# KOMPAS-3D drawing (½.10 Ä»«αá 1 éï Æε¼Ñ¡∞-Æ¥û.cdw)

Views: Вид 1, Вид 2
Referenced files in J:\РП от РУ Великорецкая\5. Проект\ПОС\Линия\Чертежи\Рис\: кран 16 т.JPG
Referenced files: Подвеска ВЧ-заградителя.cdw
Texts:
  Текст на чертеже
  Размерные надписи
  Шероховатость
  Линия-выноска #1
  Линия-выноска #2
  Линия-выноска #3
  Отклонения формы и база
  Заголовок таблицы
  Ячейка таблицы
  Стрелка вида
  Обозначение изменения
  Фигурная скобка
  Номер узла
  Марка координационной оси
  VRCB
  Выносная надпись
  Обозначение узла
  Марка/позиционное обозначение с линией-выноской
  Марка/позиционное обозначение на линии
  Марка/позиционное обозначение без линии-выноски
  ООббыыччнныыйй
  Definition Term
  Definition List
  Address
  Blockquote
  Preformatted
  Courier New
  z-Bottom of Form
  z-Top of Form
  Лит-Масса-Масштаб
  Материал-Предприятие
  Title Specification
  Body Specification ( left align )
  Body Specificaton ( centered )
  Без имени
  SPEC
  Normal
  Txt
  Body Text
  heading 1
  Знак Знак Знак Знак Знак Знак
  Verdana
  Simplex
  TXT
  txt
  MS Sans Serif
  Additional DXF text style 0
  Обычный
  Термин
  Список определений
  Адрес
  Цитаты
  Форматированный
  Z-конец формы
  Z-начало формы
  ТекстШаг1
  Title
  Денис
  header
  heading 2
  AGOpus
  footer
  NormalParagraphStyle
  Body Text 3
  ссылки
  Подпись в квадратике
  табл
  цепи
  Маркировка
  клеммы, контакты
  тексты табл
  Тексты. 3,2
  ЗОНА_привяз
  текст переноса
  ТТееррммиинн
  ССппииссоокк ооппррееддееллеенниийй
  ААддрреесс
  ЦЦииттааттыы
  ФФооррммааттиирроовваанннныыйй
  Z-ккооннеецц ффооррммыы
  Z-ннааччааллоо ффооррммыы
  GOST 2.304 type A
  rustxt
  heading 8
  heading 3
  heading 6
  heading 7
  russ
  Абзац Знак
  heading 4
  heading 5
  heading 9
  HeliosLight
  Pa3
  Pa1
  Три с половиной
  style2
  Шрифт 2.5
  Заголовки
  RUSTXT
  Table Contents
  Table Heading
  ГОСТ_МНЕ
  ESK - Обозначение
  маркировка
  ISOCP
  ROMANS
  SIMPLEX
  Обычный (веб)
  Текст 3,5
  Tahoma
  CNBNDG+TimesNewRoman
  Subtitle
  ISOCPEUR
  FR5
  romans
  Подписи
  Схема монтажа ВЧ-заградителя на опору №1.
  Отпайка ВЛ-110 кВ Тюмень - ТТЭЦ-1 3 цепь на ПС ЛПК2
  Технические характеристики крана КС-35719-1-02
  Кран КС-35719-1-02
  Примечания:
  1. Технические характеристики крана уточняются по паспорту;
  2. При выполнении всех строительно-монтажных работ на площадке необходимо руководствоваться
  требованиями СНиП 12-03-2001 "Безопасность труда в строительстве. Общие требования",
  СНиП 12-04-2002 "Безопасность труда в строительстве. Строительное производство", а также
  ПОТ Р М-016-2001, РД 153-34.0-03.150-00 "Межотраслевые правила по охране труда (правила
  безопасности) при эксплуатации электроустановок";
  3. Монтажники поднимаются на опору с помощью гидроподъёмника АГП-22 на шасси КАМАЗ-4326.
  CONTINUOUS_RGB_0_0_0_THICK_0.13
  GOST2.303 4_RGB_0_0_0_SC_0.04_THICK_0.13
  CONTINUOUS_RGB_0_0_0_THICK_0.18
  CONTINUOUS_RGB_173_173_173_THICK_0.13
  GOST2.303 4_RGB_173_173_173_SC_0.04_THICK_0.13
  СONTINUOUS_RGB_0_0_0_THICK_0.13
  POLYLINE_STYLE_0.30_RGB_0_0_0
  CONTINUOUS_RGB_0_0_0_THICK_0.3
  GOST2.303 6_RGB_0_0_0_SC_0.04_THICK_0.13
  POLYLINE_STYLE_0.18_RGB_0_0_0
  GOST2.303 6_RGB_0_0_0_SC_0_THICK_0.18
  K5LT_AXLED_RGB_255_128_0_SC_1_THICK_0.18
  CONTINUOUS_RGB_0_0_0_THICK_0.25
  POLYLINE_STYLE_0.21_RGB_0_0_0
  СONTINUOUS_RGB_0_0_0_THICK_0.18
  POLYLINE_STYLE_0.50_RGB_0_0_0
  POLYLINE_STYLE_0.40_RGB_0_0_0
  CONTINUOUS_RGB_0_0_0_THICK_0.6
  Стили документа
  Автомобильный кран КС-35714
  Ромин
  Подвеска ВЧ-заградителя
  на опоре №1
  Политова
  Разраб.
  Микрюков
  Схема пневматическая соединений
  Перезавод ВЛ на ПС Тюмень. Реконструкция устройств
  РЗ и ПА на обратных концах отходящих ВЛ,
  ВОЛС Тюменского ТПО
  ВЛ 110 кВ Тюмень-
  Тюменская ТЭЦ-1 3 цепь
  Нов.
  ГИП
  Матвеев
Dimensions and other numbers on the sheet: 16/01-ПОС; 7; 3,2_; 3.5; 2.5; 2,5; 1,8; 3,2; 2,5 (контакты, клеммы); 3,2 (надписи); 3,2 (Зоны); 5; 2,5_01; 2,5_3; 3,5_01; 3,5_tabl; 5_заголовок; 2,3_; 3,2_зона не привяз; 3,5; 3.2 маркировка; 3,2 элементы; 3,2 линия; 3,2 таблица; 2,5 грязносинь; 2.5 курсив; 2.5_Э5_надписи; 2.5_Э5_ссылки; 2.5_кабель; 3.2; 2.5 надписи; 3 и 5; 5,0_белый_подчёркнутый; 3.2 фиол; 3.2 (текст); 24600; 10500; 4000; 6100; 4800; 12; 4; 05.14; 10; 3; 253-14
